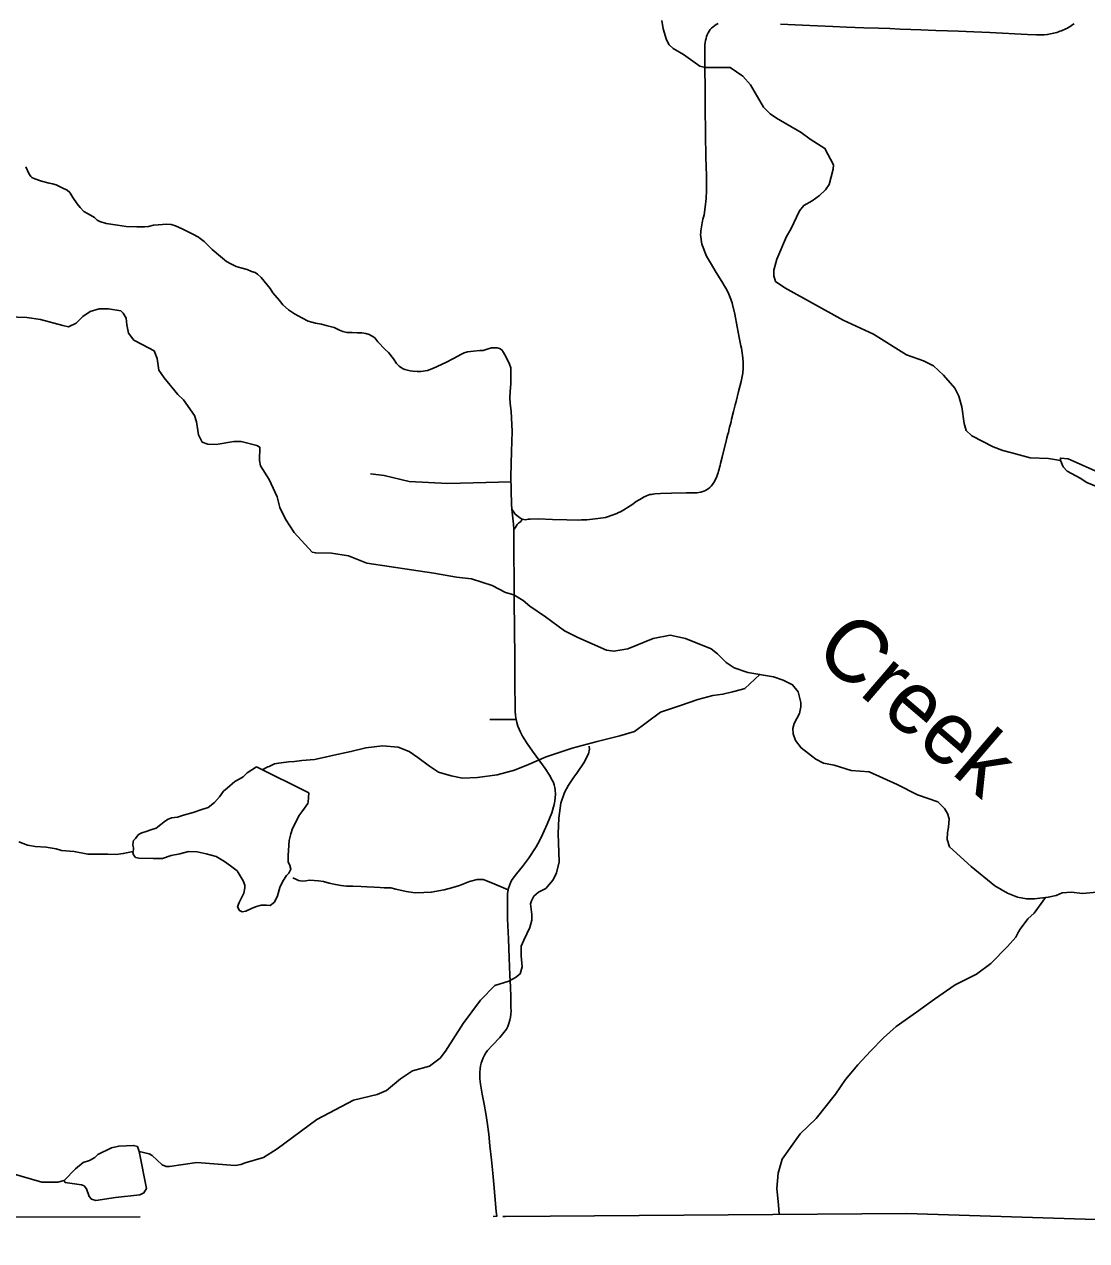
# Model space of a CAD drawing. Extents: x -19 to 366, y -4 to 359.
# Drawn here: x 140.756 to 142.109, y 186.985 to 188.535 of the extents above; entities that cross this region are included whole.
import ezdxf

# ---------------------------------------------------------------- set-up
doc = ezdxf.new("R2010")
doc.units = 0
for name, color, linetype in [('R_Alt Surface', 7, 'Continuous'), ('R_ROW', 7, 'Continuous'), ('R_ROW Annot', 7, 'Continuous'), ('R_Temp Easement', 7, 'Continuous'), ('Sheet Fence', 7, 'Continuous')]:
    doc.layers.add(name, color=color, linetype=linetype)

msp = doc.modelspace()

# ---------------------------------------------------------------- linework, layer by layer
at = {"layer": 'R_Alt Surface'}
for points in [[(139.3808, 187.0227), (139.457, 187.0215), (139.699, 187.0177), (139.7422, 187.017), (140.378, 187.0152), (140.9038, 187.0155)], [(141.3656, 187.0158), (141.3691, 187.0158), (141.8799, 187.0199), (142.4018, 187.003), (142.3602, 186.0117)]]:
    msp.add_lwpolyline(points, dxfattribs=at)
at = {"layer": 'R_ROW'}
for points in [[(141.6399, 188.536), (141.6377, 188.5349), (141.6356, 188.5336), (141.6336, 188.532), (141.6317, 188.5303), (141.63, 188.5283), (141.6285, 188.5263), (141.6272, 188.5241), (141.6261, 188.5217), (141.6253, 188.5197), (141.6246, 188.5171), (141.624, 188.5144), (141.6235, 188.5117), (141.6232, 188.509), (141.623, 188.5069), (141.623, 188.5033), (141.623, 188.4943), (141.6232, 188.4709), (141.6234, 188.4613), (141.6234, 188.4394), (141.6236, 188.419), (141.6238, 188.4059), (141.6239, 188.3954), (141.6241, 188.3854), (141.6243, 188.375), (141.6244, 188.3658), (141.625, 188.3421), (141.6251, 188.3384), (141.6252, 188.3346), (141.6251, 188.3233), (141.6249, 188.3129)], [(142.0937, 188.5358), (142.092, 188.5346), (142.0903, 188.5335), (142.0885, 188.5324), (142.0867, 188.5313), (142.0849, 188.5303), (142.083, 188.5293), (142.0812, 188.5284), (142.0793, 188.5276), (142.0773, 188.5268), (142.0754, 188.5261), (142.0734, 188.5254), (142.0714, 188.5248), (142.0694, 188.5242), (142.0674, 188.5237), (142.0653, 188.5232), (142.0633, 188.5228), (142.0592, 188.522), (142.0553, 188.5218), (142.0508, 188.5217), (142.0457, 188.5218), (142.0341, 188.5221), (141.9863, 188.5245), (141.9658, 188.5253), (141.9462, 188.5261), (141.9322, 188.5266), (141.9174, 188.5273), (141.8983, 188.528), (141.8855, 188.5285), (141.8719, 188.529), (141.8589, 188.5295), (141.8442, 188.53), (141.8258, 188.5307), (141.8034, 188.5315), (141.7863, 188.5323), (141.7567, 188.5334), (141.7196, 188.5351)], [(141.6249, 188.3129), (141.6237, 188.3019), (141.6221, 188.2922), (141.6212, 188.2892), (141.6206, 188.2868), (141.62, 188.2844), (141.6195, 188.2819), (141.6191, 188.2795), (141.6187, 188.277), (141.6183, 188.2745), (141.6181, 188.272), (141.6179, 188.2695), (141.6177, 188.267), (141.6194, 188.255), (141.62, 188.2529), (141.6208, 188.2506), (141.6216, 188.2484), (141.6225, 188.2461), (141.6234, 188.2439), (141.6244, 188.2417), (141.6254, 188.2395), (141.6265, 188.2374), (141.6277, 188.2352), (141.6288, 188.2331), (141.6301, 188.2311), (141.6377, 188.2188), (141.6449, 188.2074), (141.649, 188.2), (141.6505, 188.1974), (141.6516, 188.1953), (141.6526, 188.1932), (141.6536, 188.1911), (141.6545, 188.1889), (141.6554, 188.1868), (141.6562, 188.1846), (141.657, 188.1824), (141.6577, 188.1801), (141.6583, 188.1779), (141.6612, 188.1655), (141.6642, 188.1495), (141.6666, 188.1361), (141.669, 188.1254), (141.6696, 188.1224), (141.6702, 188.1193), (141.6707, 188.1163), (141.6712, 188.1132), (141.6716, 188.1102), (141.672, 188.1036), (141.6721, 188.1009), (141.672, 188.0988), (141.672, 188.0967), (141.6718, 188.0946), (141.6716, 188.0925), (141.6714, 188.0904), (141.6711, 188.0883), (141.6707, 188.0862), (141.6703, 188.0841), (141.6698, 188.0821), (141.6692, 188.08), (141.6661, 188.0672), (141.6629, 188.0545), (141.6618, 188.0503), (141.6597, 188.0417), (141.6572, 188.0317), (141.6564, 188.0286), (141.6552, 188.0241), (141.6546, 188.0219), (141.6541, 188.0196), (141.653, 188.0151), (141.6524, 188.0128), (141.6513, 188.0082), (141.6508, 188.006), (141.6453, 187.9836), (141.6431, 187.9755), (141.6425, 187.9727), (141.6419, 187.9704), (141.6413, 187.9681), (141.6406, 187.9657), (141.6399, 187.9635), (141.6391, 187.9612), (141.6382, 187.9589), (141.6373, 187.9567), (141.6363, 187.9545), (141.6353, 187.9523), (141.633, 187.9487), (141.6313, 187.9467), (141.6294, 187.9449), (141.6274, 187.9433), (141.6252, 187.9418), (141.6245, 187.9415)], [(141.5458, 187.9329), (141.545, 187.9324), (141.5431, 187.9313), (141.5358, 187.927), (141.5302, 187.9228), (141.5247, 187.9192), (141.5221, 187.9176), (141.5199, 187.9164), (141.5177, 187.9152), (141.5155, 187.914), (141.5132, 187.9129), (141.511, 187.9119), (141.5086, 187.9109), (141.5063, 187.91), (141.4964, 187.9067), (141.4935, 187.9062), (141.4901, 187.9057), (141.4866, 187.9052), (141.4832, 187.9048), (141.4798, 187.9044), (141.4763, 187.9041), (141.4729, 187.9038), (141.4694, 187.9036), (141.466, 187.9035), (141.4625, 187.9034), (141.4471, 187.9035), (141.429, 187.9041), (141.4106, 187.9049), (141.4007, 187.9045), (141.3982, 187.9044), (141.3946, 187.9037), (141.3905, 187.9043)], [(141.6245, 187.9415), (141.6229, 187.9406), (141.6204, 187.9396), (141.618, 187.9388), (141.6154, 187.9383), (141.6128, 187.938), (141.6102, 187.9379), (141.5992, 187.938), (141.5805, 187.9377), (141.5666, 187.9372), (141.5594, 187.9367), (141.5571, 187.9365), (141.555, 187.9361), (141.5529, 187.9357), (141.5508, 187.935), (141.5488, 187.9343), (141.5469, 187.9334), (141.5458, 187.9329)], [(141.3905, 187.9043), (141.3886, 187.9013), (141.3855, 187.8993), (141.3839, 187.8976), (141.3826, 187.8957), (141.3816, 187.8936), (141.3796, 187.8913)], [(141.3828, 187.6494), (141.382, 187.6544), (141.3815, 187.6599), (141.3814, 187.6648), (141.3813, 187.6706), (141.3812, 187.6881), (141.3811, 187.7019), (141.3809, 187.7178), (141.3809, 187.7356), (141.3807, 187.7571), (141.3806, 187.7733), (141.3804, 187.7916), (141.3804, 187.8083), (141.3803, 187.8106), (141.3803, 187.8175), (141.3801, 187.8284), (141.38, 187.8357), (141.3798, 187.8517), (141.3798, 187.8612), (141.3796, 187.8751), (141.3799, 187.8845), (141.3797, 187.889), (141.3796, 187.8913)], [(141.3726, 187.4323), (141.3731, 187.4344), (141.3741, 187.4377), (141.3754, 187.4409), (141.377, 187.4439), (141.3789, 187.4468), (141.3831, 187.4524), (141.3907, 187.4619), (141.3984, 187.4722), (141.4082, 187.4869), (141.4103, 187.4908), (141.4146, 187.499), (141.4186, 187.5074), (141.4224, 187.5159), (141.4281, 187.5304), (141.4311, 187.5408), (141.432, 187.5451), (141.4325, 187.5496), (141.4328, 187.5538), (141.4326, 187.5595), (141.432, 187.5627), (141.4312, 187.5659), (141.4301, 187.5689), (141.4287, 187.5719), (141.4253, 187.5783), (141.4196, 187.5867), (141.4129, 187.5961), (141.4037, 187.6089), (141.3968, 187.6187), (141.3909, 187.628), (141.3881, 187.6331), (141.385, 187.6405), (141.3836, 187.6454), (141.3828, 187.6494)], [(141.3726, 187.4323), (141.3719, 187.4276), (141.3717, 187.4246), (141.3719, 187.3952), (141.3728, 187.3699), (141.3737, 187.3455), (141.3748, 187.3232), (141.3754, 187.3085), (141.3759, 187.2959), (141.3761, 187.282), (141.3762, 187.2779), (141.3759, 187.2739), (141.3754, 187.2699), (141.3746, 187.2659), (141.3734, 187.262), (141.372, 187.2582), (141.3704, 187.2546), (141.3621, 187.2441), (141.3526, 187.2344), (141.3464, 187.2273), (141.3443, 187.2244), (141.3424, 187.2214), (141.3407, 187.2182), (141.3394, 187.2148), (141.3383, 187.2114), (141.3375, 187.208), (141.3369, 187.2039), (141.3365, 187.1996), (141.3364, 187.1954), (141.3366, 187.1912), (141.3374, 187.1846), (141.3395, 187.1718), (141.3418, 187.1591), (141.344, 187.1472), (141.3457, 187.1363), (141.3479, 187.1206), (141.3494, 187.1058), (141.3512, 187.088), (141.353, 187.0709), (141.3543, 187.0569), (141.3557, 187.0422), (141.3574, 187.0223), (141.358, 187.0163), (141.3581, 187.0158)]]:
    msp.add_lwpolyline(points, dxfattribs=at)
at = {"layer": 'R_ROW Annot'}
for points in [[(140.8321, 188.2967), (140.8273, 188.3015), (140.8235, 188.3063), (140.8178, 188.3142), (140.814, 188.3208), (140.8107, 188.3238), (140.8046, 188.3268), (140.7967, 188.3303), (140.7922, 188.3317), (140.7879, 188.3327), (140.778, 188.3351), (140.7694, 188.338), (140.7657, 188.3397), (140.7644, 188.3412), (140.7621, 188.3451), (140.7581, 188.3535)], [(141.3774, 187.917), (141.3767, 187.9236), (141.3761, 187.959), (141.3768, 187.9908), (141.3776, 188.016), (141.3764, 188.0419), (141.375, 188.0517), (141.3747, 188.0592), (141.3753, 188.0672), (141.3758, 188.0768), (141.3761, 188.0891), (141.3758, 188.0973), (141.3744, 188.1019), (141.37, 188.111), (141.3667, 188.1167), (141.3644, 188.1202), (141.3613, 188.122), (141.3586, 188.1229), (141.3554, 188.1229), (141.3514, 188.1228), (141.3469, 188.1214), (141.3407, 188.1193), (141.3366, 188.1192), (141.3285, 188.1186), (141.3209, 188.1178), (141.3165, 188.1164), (141.313, 188.1147), (141.3029, 188.1091), (141.2931, 188.1039), (141.2774, 188.0968), (141.2697, 188.0938), (141.2615, 188.0926), (141.2567, 188.0926), (141.251, 188.0931), (141.2475, 188.0936), (141.2408, 188.0952), (141.2379, 188.0965), (141.2336, 188.0993), (141.2301, 188.103), (141.2264, 188.1088), (141.2199, 188.1167), (141.2159, 188.1206), (141.2067, 188.1303), (141.2025, 188.1355), (141.1995, 188.1376), (141.1953, 188.1396), (141.1912, 188.141), (141.1862, 188.1417), (141.1803, 188.142), (141.1737, 188.1422), (141.1669, 188.1424), (141.1621, 188.1435), (141.1576, 188.1455), (141.151, 188.1487), (141.1409, 188.1514), (141.1348, 188.1528), (141.1273, 188.1541), (141.1176, 188.1569), (141.1097, 188.1609), (141.1005, 188.1661), (141.0929, 188.1711), (141.0857, 188.1774), (141.0811, 188.183), (141.0728, 188.1929), (141.0693, 188.1986), (141.0578, 188.2126), (141.0532, 188.2165), (141.0501, 188.2187), (141.0456, 188.2202), (141.0399, 188.2226), (141.0322, 188.2247), (141.0259, 188.2266), (141.0192, 188.2298), (141.0138, 188.2329), (141.006, 188.2391), (140.9957, 188.2482), (140.9854, 188.2582), (140.9804, 188.2622), (140.978, 188.2637), (140.9708, 188.2675), (140.9582, 188.2742), (140.949, 188.2784), (140.9432, 188.2798), (140.9375, 188.2803), (140.9324, 188.2801), (140.9266, 188.2795), (140.9207, 188.2791), (140.9142, 188.2775), (140.9095, 188.2771), (140.9042, 188.2769), (140.8996, 188.2768), (140.886, 188.2773), (140.8747, 188.2792), (140.8605, 188.2813), (140.8525, 188.2836), (140.8491, 188.2856), (140.8454, 188.2887), (140.8407, 188.2919), (140.8368, 188.2941), (140.8321, 188.2967)], [(141.3762, 187.952), (141.2958, 187.95), (141.2465, 187.9525), (141.2145, 187.9602), (141.1972, 187.9622)], [(141.3796, 187.8913), (141.3794, 187.8981), (141.3774, 187.917)], [(141.3905, 187.9043), (141.3875, 187.9061), (141.3851, 187.908), (141.3814, 187.911), (141.3774, 187.917)], [(141.3828, 187.6494), (141.3724, 187.649), (141.3627, 187.6494), (141.3494, 187.6491)], [(141.0983, 187.4475), (141.1029, 187.4452), (141.1054, 187.4441), (141.1104, 187.4434), (141.1146, 187.4437), (141.1194, 187.4443), (141.1253, 187.4442), (141.1311, 187.4435), (141.1372, 187.4427), (141.1447, 187.4407), (141.1528, 187.4388), (141.1597, 187.4376), (141.1664, 187.4369), (141.1748, 187.4368), (141.1851, 187.4364), (141.1927, 187.436), (141.2017, 187.4355), (141.2094, 187.435), (141.2145, 187.4349), (141.2232, 187.4347), (141.2295, 187.4329), (141.2428, 187.4299), (141.2542, 187.4285), (141.2651, 187.4289), (141.2745, 187.4291), (141.2909, 187.4322), (141.302, 187.4351), (141.3105, 187.4376), (141.3232, 187.4426), (141.3331, 187.4452), (141.3405, 187.4454), (141.3463, 187.443), (141.3555, 187.4393), (141.3665, 187.4345), (141.3726, 187.4323)], [(141.3533, 187.0158), (141.358, 187.0163)]]:
    msp.add_lwpolyline(points, dxfattribs=at)
at = {"layer": 'R_Temp Easement'}
for points in [[(141.5685, 188.5401), (141.57, 188.5291), (141.5741, 188.5154), (141.5775, 188.509), (141.5828, 188.5044), (141.5961, 188.4964), (141.6165, 188.4816), (141.6237, 188.4801), (141.6554, 188.4801), (141.6713, 188.4691), (141.6811, 188.4581), (141.6977, 188.4296), (141.7064, 188.4209), (141.7144, 188.4156), (141.7457, 188.3973), (141.7574, 188.3886), (141.776, 188.3768), (141.7869, 188.3559), (141.7865, 188.3503), (141.7816, 188.3309), (141.7767, 188.3241), (141.7692, 188.3168), (141.7597, 188.31), (141.7491, 188.3043), (141.7435, 188.2975), (141.7325, 188.274), (141.7272, 188.2645), (141.7147, 188.2356), (141.711, 188.2216), (141.711, 188.2147), (141.7132, 188.2075), (141.7249, 188.1992), (141.7994, 188.1582), (141.8379, 188.1403), (141.8799, 188.1137), (141.9018, 188.1061), (141.9143, 188.0997), (141.9271, 188.0879), (141.9415, 188.0712), (141.9468, 188.0613), (141.9506, 188.0477), (141.9532, 188.0264)], [(140.7227, 188.1629), (140.7593, 188.1614), (140.7767, 188.1591), (140.8051, 188.1511), (140.8126, 188.1496), (140.8224, 188.1541), (140.8308, 188.1629), (140.8402, 188.169), (140.8515, 188.1724), (140.8636, 188.1724), (140.8791, 188.1701), (140.8822, 188.167), (140.8859, 188.1606), (140.8867, 188.1519), (140.889, 188.1416), (140.8958, 188.1325), (140.9063, 188.1272), (140.9215, 188.1188), (140.9256, 188.109), (140.9275, 188.0945), (140.9343, 188.0847), (140.9517, 188.0634), (140.9589, 188.0566), (140.9732, 188.0364), (140.9755, 188.0285), (140.9781, 188.0121), (140.9827, 188.0027)], [(141.9532, 188.0264), (141.9558, 188.0173), (141.963, 188.0108), (141.9902, 187.9968), (142.0027, 187.9919), (142.014, 187.9892), (142.0375, 187.9827), (142.0609, 187.9816), (142.076, 187.9793)], [(140.9827, 188.0027), (140.9899, 188), (141.0004, 187.9996), (141.0231, 188.0034), (141.0326, 188.0034), (141.0526, 187.9985), (141.0564, 187.9962), (141.0556, 187.9791), (141.0571, 187.9723), (141.0681, 187.9548), (141.0783, 187.9328), (141.0817, 187.9195), (141.0889, 187.9043), (141.0998, 187.8876), (141.1229, 187.8625), (141.1274, 187.8614), (141.1475, 187.861), (141.169, 187.8576), (141.1924, 187.8485), (141.2778, 187.8356), (141.3069, 187.8306), (141.3258, 187.8283), (141.3523, 187.82), (141.3693, 187.8109), (141.3799, 187.8082), (141.3916, 187.801), (141.4003, 187.7938), (141.4203, 187.7801), (141.4441, 187.7623), (141.4611, 187.7535), (141.4978, 187.7376), (141.5072, 187.7361), (141.525, 187.7391), (141.5571, 187.7524), (141.579, 187.7566), (141.5983, 187.7524), (141.6312, 187.7391), (141.6391, 187.733), (141.6501, 187.722), (141.6603, 187.7152), (141.6777, 187.7091), (141.7106, 187.7034), (141.723, 187.6992), (141.7348, 187.6935), (141.7419, 187.6844), (141.7453, 187.6707), (141.7453, 187.6654), (141.7438, 187.6567), (141.737, 187.6442), (141.7351, 187.6377), (141.7355, 187.6309), (141.7385, 187.6225), (141.7457, 187.613), (141.7646, 187.5986), (141.7744, 187.5937), (141.7877, 187.591), (141.8096, 187.5842), (141.8326, 187.5823), (141.8682, 187.5663), (141.8939, 187.5534), (141.9199, 187.5443), (141.9282, 187.5356), (141.932, 187.5295), (141.9343, 187.5226), (141.9335, 187.512), (141.932, 187.5052)], [(142.076, 187.9793), (142.076, 187.9823), (142.0858, 187.9812), (142.1354, 187.9592), (142.1406, 187.9558), (142.1486, 187.9482), (142.1452, 187.9402), (142.1433, 187.9387), (142.1403, 187.9383), (142.1097, 187.9512), (142.101, 187.9569), (142.0847, 187.9656), (142.0794, 187.971), (142.076, 187.9793)], [(141.6931, 187.7064), (141.6739, 187.6889), (141.6696, 187.6875), (141.6581, 187.6844), (141.6461, 187.6813), (141.6331, 187.6798), (141.614, 187.6745), (141.592, 187.6672), (141.5665, 187.6584), (141.5483, 187.6451), (141.5333, 187.6338), (141.5149, 187.6285), (141.486, 187.6212), (141.4541, 187.6125), (141.4209, 187.6015), (141.3983, 187.5917), (141.3805, 187.5845), (141.3585, 187.5785), (141.3333, 187.5751), (141.3144, 187.5745), (141.3, 187.5774), (141.2837, 187.5819), (141.2725, 187.5898), (141.2576, 187.6007), (141.2464, 187.6084), (141.2325, 187.6138), (141.2124, 187.6158), (141.1914, 187.6131), (141.1722, 187.6083), (141.1504, 187.6036), (141.1395, 187.6011), (141.126, 187.5983), (141.1099, 187.5968), (141.1005, 187.5957), (141.0928, 187.5951), (141.0898, 187.5947), (141.0802, 187.5937), (141.0751, 187.5926), (141.068, 187.5894), (141.0665, 187.589), (141.0592, 187.585)], [(141.456, 187.5756), (141.4601, 187.581), (141.4689, 187.5941), (141.475, 187.6054), (141.4763, 187.6115), (141.4758, 187.6152)], [(141.0518, 187.5887), (141.0399, 187.5812), (141.0349, 187.5762), (141.0298, 187.5732), (141.0242, 187.5701), (141.0146, 187.5619), (141.0098, 187.5578), (141.0049, 187.5507), (140.9986, 187.5433), (140.9903, 187.5369), (140.9809, 187.5342), (140.9713, 187.5308), (140.9589, 187.5271), (140.9513, 187.5246), (140.9437, 187.5241), (140.9387, 187.5219), (140.9344, 187.5189), (140.9299, 187.5154), (140.924, 187.5109), (140.9174, 187.5087), (140.9113, 187.5065), (140.906, 187.5048), (140.9032, 187.5036), (140.9012, 187.5021), (140.898, 187.4976), (140.8953, 187.4951), (140.8948, 187.4932), (140.8945, 187.489), (140.8951, 187.4858), (140.8952, 187.483), (140.8945, 187.4797), (140.8953, 187.4767), (140.898, 187.4732), (140.902, 187.4725), (140.9204, 187.472), (140.9323, 187.4722), (140.9431, 187.4757), (140.9544, 187.4782), (140.9653, 187.4808), (140.9763, 187.4806), (140.988, 187.478), (141.0004, 187.4747), (141.0113, 187.4681), (141.0188, 187.4628), (141.0272, 187.4562), (141.0325, 187.4479), (141.0349, 187.4436), (141.0369, 187.4382), (141.037, 187.4346), (141.0358, 187.4277), (141.032, 187.4204), (141.0301, 187.4158), (141.0279, 187.4103), (141.0303, 187.4058), (141.0339, 187.4043), (141.0383, 187.4048), (141.0465, 187.4086), (141.0521, 187.4108), (141.0579, 187.4125), (141.0647, 187.4126), (141.0692, 187.4123), (141.0748, 187.4163), (141.0786, 187.4243), (141.0816, 187.4352), (141.0857, 187.4434), (141.0903, 187.4504), (141.093, 187.4535), (141.0959, 187.4586), (141.0945, 187.4632), (141.0921, 187.4679), (141.0921, 187.4758), (141.0934, 187.4948), (141.0955, 187.5034), (141.098, 187.5103), (141.1025, 187.5191), (141.1061, 187.5264), (141.1097, 187.5316), (141.1132, 187.536), (141.1174, 187.542), (141.1176, 187.5437), (141.1186, 187.5557)], [(141.0518, 187.5887), (141.1186, 187.5557)], [(141.456, 187.5756), (141.4494, 187.5656), (141.4445, 187.5561), (141.4396, 187.5425), (141.4369, 187.5235), (141.4362, 187.5038), (141.4377, 187.4677), (141.4343, 187.454), (141.4298, 187.4449), (141.4207, 187.4339), (141.4112, 187.429), (141.4052, 187.424), (141.4022, 187.4183), (141.401, 187.4142), (141.4029, 187.4009), (141.4029, 187.3937), (141.4003, 187.3842), (141.3923, 187.3682), (141.3893, 187.3603), (141.3889, 187.3481), (141.3905, 187.3341), (141.3878, 187.3253), (141.3818, 187.3204), (141.3734, 187.3158), (141.3557, 187.3102), (141.3372, 187.2916), (141.3152, 187.262), (141.2926, 187.2267), (141.2858, 187.2175), (141.2725, 187.2073), (141.2506, 187.2016), (141.2355, 187.1914), (141.2177, 187.1766), (141.2056, 187.1712), (141.1754, 187.164), (141.1289, 187.1394), (141.0783, 187.1022), (141.0609, 187.0912), (141.0375, 187.0843), (141.0322, 187.0821), (141.0246, 187.0809), (140.9759, 187.0847), (140.9411, 187.0794), (140.9369, 187.0794), (140.9316, 187.0817), (140.9192, 187.0938), (140.9154, 187.0957), (140.9025, 187.0988), (140.9003, 187.1049), (140.8954, 187.1064), (140.8765, 187.1056), (140.8674, 187.1033), (140.85, 187.095), (140.8459, 187.0912), (140.8391, 187.0874), (140.8311, 187.0847), (140.8213, 187.0768), (140.8069, 187.0616), (140.799, 187.0597), (140.7786, 187.0597), (140.7389, 187.0711)], [(141.932, 187.5052), (141.9316, 187.4961), (141.9347, 187.487), (141.9623, 187.4619), (141.9925, 187.4372), (142.0084, 187.4277), (142.0212, 187.4228), (142.0329, 187.4205), (142.0428, 187.4205), (142.0605, 187.4228), (142.0707, 187.4251), (142.0783, 187.4285), (142.09, 187.4292), (142.104, 187.4273), (142.1225, 187.4292)], [(140.8947, 187.4809), (140.8823, 187.4783), (140.873, 187.4772), (140.8626, 187.4775), (140.8498, 187.4776), (140.8371, 187.4777), (140.8195, 187.4809), (140.8034, 187.4824), (140.7967, 187.4842), (140.784, 187.4867), (140.77, 187.4874), (140.7604, 187.4892), (140.7493, 187.4932)], [(141.7178, 187.0186), (141.7168, 187.0307), (141.7146, 187.0515), (141.7164, 187.0709), (141.7217, 187.089), (141.7445, 187.1212), (141.7649, 187.1406), (141.7897, 187.1719), (141.8021, 187.1906), (141.8181, 187.2091), (141.8343, 187.2264), (141.8507, 187.2436), (141.8668, 187.258), (141.8928, 187.2762), (141.9157, 187.293), (141.9421, 187.3111), (141.9693, 187.3248), (141.9873, 187.3383), (142.0086, 187.3598), (142.0194, 187.372), (142.0227, 187.3787), (142.0247, 187.382), (142.0346, 187.3951), (142.0427, 187.4023), (142.0571, 187.4224)], [(140.8069, 187.0616), (140.8081, 187.0593), (140.8292, 187.0563), (140.8323, 187.0548), (140.8353, 187.0513), (140.8387, 187.0415), (140.8417, 187.0381), (140.8474, 187.0362), (140.8723, 187.0399), (140.9033, 187.0434), (140.9086, 187.046), (140.912, 187.0517), (140.9025, 187.0988)]]:
    msp.add_lwpolyline(points, dxfattribs=at)
at = {"layer": 'Sheet Fence'}
for points in [[(146.7783, 1.697), (146.5788, 10.3131), (146.3785, 18.9294), (146.1776, 27.5458), (145.9759, 36.1624), (145.7736, 44.7791), (145.5705, 53.396), (145.3668, 62.013), (145.1624, 70.6301), (144.9572, 79.2474), (144.7514, 87.8648), (144.5449, 96.4823), (144.3377, 105.1), (144.1299, 113.7179), (143.9213, 122.3359), (143.712, 130.954), (143.5021, 139.5723), (143.2915, 148.1907), (143.0802, 156.8092), (142.8682, 165.4279), (142.6555, 174.0468), (142.4422, 182.6658), (142.2282, 191.2849), (142.0135, 199.9042), (141.7981, 208.5236), (141.582, 217.1432), (141.3653, 225.7629), (141.1479, 234.3828), (140.9298, 243.0028), (140.711, 251.623), (140.4916, 260.2433), (140.2715, 268.8638), (140.0508, 277.4844), (139.8293, 286.1051), (139.6072, 294.726), (139.3845, 303.3471), (139.161, 311.9683), (138.937, 320.5896), (138.7122, 329.2111), (138.4868, 337.8328), (138.2607, 346.4546)], [(0, 180.8999), (7.1228, 180.9044), (14.2457, 180.9176), (21.3685, 180.9397), (28.4912, 180.9706), (35.614, 181.0103), (42.7366, 181.0589), (49.8592, 181.1163), (56.9818, 181.1825), (64.1042, 181.2575), (71.2266, 181.3414), (78.3488, 181.4341), (85.4709, 181.5357), (92.5929, 181.646), (99.7147, 181.7652), (106.8364, 181.8933), (113.9579, 182.0301), (121.0793, 182.1758), (128.2005, 182.3303), (135.3214, 182.4936), (142.4422, 182.6658), (149.5627, 182.8468), (156.683, 183.0366), (163.8031, 183.2352), (170.9229, 183.4427), (178.0425, 183.659), (185.1617, 183.8841), (192.2807, 184.1181), (199.3994, 184.3608), (206.5178, 184.6124), (213.6359, 184.8728), (220.7537, 185.1421), (227.8711, 185.4201), (234.9881, 185.707), (242.1048, 186.0027), (249.2212, 186.3073), (256.3371, 186.6206), (263.4526, 186.9428), (270.5678, 187.2738), (277.6825, 187.6136), (284.7968, 187.9622), (291.9107, 188.3197), (299.0241, 188.6859), (306.1371, 189.061), (313.2495, 189.4449), (320.3615, 189.8377), (327.4731, 190.2392), (334.5841, 190.6495), (341.6946, 191.0687)]]:
    msp.add_spline(points, degree=3, dxfattribs=at)

# ---------------------------------------------------------------- texts
at = {"layer": 'R_Temp Easement'}
msp.add_text('Creek', height=0.08, rotation=319.3735, dxfattribs=at).set_placement((141.7596, 187.7322))

doc.saveas('drawing.dxf')
